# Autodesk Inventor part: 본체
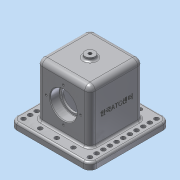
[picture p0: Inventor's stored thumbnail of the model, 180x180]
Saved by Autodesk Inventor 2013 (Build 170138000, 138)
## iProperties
Created: 2018-11
Part Number: 본체
Material: 알루미늄 6061
Document SubType Name: Modeling
Designer: dgall
Density: 2.71 g/cm^3
Mass: 1020.76 g
Surface Area: 777.082 cm^2
Volume: 376.663 cm^3
Author: dgall
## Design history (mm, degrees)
sketch "스케치1"
  geometry: L1 (-40, 40)-(40, 40); L2 (40, 40)-(40, -40); L3 (40, -40)-(-40, -40); L4 (-40, -40)-(-40, 40); L5 (-60, 60)-(60, 60); L6 (60, 60)-(60, -60); L7 (60, -60)-(-60, -60); L8 (-60, -60)-(-60, 60); L9 (-30, 23)-(30, 23); L10 (30, 23)-(30, -23); L11 (30, -23)-(-30, -23); L12 (-30, -23)-(-30, 23); 7 further points
  constraints: 24 end point, 6 midpoint, 6 parallel, 5 perpendicular, 3 horizontal, 3 horizontal alignment, 3 vertical alignment
  dimensions: "d0" = 80 distance of L1.start L1.end; "d2" = 120 distance of L5.start L5.end; "d14" = 60 distance of L9.start L9.end; "d15" = 46 distance of L11.end L9.start
extrude "돌출1" new body sketch "스케치1" distance "d3" = 90; taper "d4" = 0 deg
extrude "돌출2" join sketch "스케치1" distance "d5" = 10; taper "d6" = 0 deg
sketch "스케치2"
  geometry: L1 (60, 10)-(60, 0) reference; L2 (60, 0)-(-60, 0) reference; L3 (-60, 0)-(-60, 10) reference; L4 (-60, 10)-(-40, 10) reference; L5 (-40, 10)-(-40, 90) reference; L6 (-40, 90)-(40, 90) reference; L7 (40, 90)-(40, 10) reference; L8 (40, 10)-(60, 10) reference; L9 (-40, 48)-(40, 48); L10 (-40, 68)-(-26, 68); L11 (-26, 68)-(-26, 64.5); L12 (-26, 64.5)-(-23, 64.5); L13 (-23, 64.5)-(-23, 48); L14 (23, 64.5)-(26, 64.5); L15 (26, 64.5)-(26, 68); L16 (26, 68)-(40, 68); L17 (23, 64.5)-(23, 48); 1 further point
  constraints: 18 end point, 6 point on line, 5 parallel, 5 perpendicular, 3 equal length, 1 horizontal alignment
  dimensions: "d7" = 48 distance between parallel lines of L2 L9; "d8" = 14 distance of L10.start L10.end; "d9" = 3 distance of L11.end L12.end; "d11" = 40 diameter of L10 L9; "d12" = 33 diameter of L12 L9
revolve "회전1" sketch "스케치2" stored, may be unused: angle "d13" = 90 deg
extrude "돌출3" cut sketch "스케치1" distance "d16" = 80; taper "d17" = 0 deg
node "작업 평면1"
sketch "스케치5"
  geometry: C1 r 7.5 at (0, 0); 1 further point
  constraints: 1 centre point, 1 coincident
  dimensions: "d52" = 15 diameter of C1
extrude "돌출4" join sketch "스케치5" stored distance "d53" = 80; taper "d54" = 0 deg
hole "구멍3" diameter "d57" = 4.917; stored, may be unused: countersink angle "d61" = 90 deg, drill point angle "d63" = 0 deg; dims "d58" = 3, "d59" = 4, "d60" = 2, "d62" = 8, "d117" = 10, "d118" = 10
sketch "스케치6"
  geometry: C1 r 20 at (40, -42) reference; 2 further points
  constraints: 1 vertical alignment
  dimensions: "d64" = 26 distance of C1.centre point (40, -16)
hole "구멍4" sketch "스케치6" at (40, -16) diameter "d65" = 3.242; stored, may be unused: countersink angle "d69" = 90 deg, drill point angle "d71" = 118 deg; dims "d66" = 8, "d67" = 4, "d68" = 2, "d70" = 10
fillet "모깎기1" dims "d75" = 8
fillet "모깎기2" dims "d76" = 8
fillet "모깎기3" dims "d77" = 3
fillet "모깎기4" dims "d78" = 0.6
chamfer "모따기1" distance "d79" = 1; stored, may be unused: second distance "d80" = 2, angle "d81" = 45 deg
fillet "모깎기5" dims "d82" = 10
fillet "모깎기6" dims "d83" = 3
fillet "모깎기7" dims "d84" = 3
fillet "모깎기8" dims "d85" = 3
fillet "모깎기9" dims "d86" = 3
sketch "스케치7"
  geometry: A1 r 7 centre (-50, -50) between (-57, -50) and (-50, -57) reference; 4 further points
  constraints: 3 horizontal alignment
  dimensions: "d87" = 25 distance of A1.centre point (-25, -50); "d88" = 25 distance of point (-25, -50) point (0, -50); "d89" = 25 distance of point (25, -50) point (0, -50)
hole "구멍5" sketch "스케치7" at (-25, -50), (0, -50), (25, -50) diameter "d90" = 6.6; stored, may be unused: countersink angle "d94" = 90 deg, drill point angle "d96" = 0 deg; dims "d91" = 6.6, "d92" = 4, "d93" = 2, "d95" = 10
sketch "스케치8"
  geometry: A1 r 7 centre (-50, -50) between (-57, -50) and (-50, -57) reference; A2 r 7 centre (-50, 50) between (-50, 57) and (-57, 50) reference; 12 further points
  constraints: 10 vertical alignment, 2 coincident
  dimensions: "d97" = 10 distance of point (-50, -40) point (-50, -50); "d99" = 10 distance of point (-50, -30) point (-50, -40); "d100" = 10 distance of point (-50, -20) point (-50, -30); "d101" = 10 distance of point (-50, -10) point (-50, -20); "d102" = 10 distance of point (-50, 0) point (-50, -10); "d103" = 10 distance of point (-50, 10) point (-50, 0); "d104" = 10 distance of point (-50, 20) point (-50, 10); "d105" = 10 distance of point (-50, 30) point (-50, 20); "d106" = 10 distance of point (-50, 40) point (-50, 30)
hole "구멍6" sketch "스케치8" at (-50, 50), (-50, 40), (-50, 30), (-50, 20), (-50, 10), (-50, 0), (-50, -10), (-50, -20), (-50, -30), (-50, -40), (-50, -50) diameter "d107" = 6.6; stored, may be unused: countersink angle "d111" = 90 deg, drill point angle "d113" = 0 deg; dims "d108" = 6.6, "d109" = 4, "d110" = 2, "d112" = 10
sketch "스케치9"
  geometry: L1 (82, 82)-(82, -18) reference; 3 further points
  constraints: 1 horizontal alignment, 1 midpoint, 1 other
  dimensions: "d114" = 48 distance from line of L1 point (34, 32)
feature "엠보싱1" sketch "스케치9" dims "d0" = 80, "d2" = 120, "d7" = 48, "d8" = 14, "d9" = 3, "d11" = 40, "d12" = 33, "d115" = 0.5, "d116" = 0
node "솔리드1"
pattern_circular "원형 패턴1" dims angle "d73" = 360 deg
mirror "대칭3"
mirror "대칭4"
mirror "대칭5"
node "절단 모서리 투영1"
other parameters: "d51" = 5
